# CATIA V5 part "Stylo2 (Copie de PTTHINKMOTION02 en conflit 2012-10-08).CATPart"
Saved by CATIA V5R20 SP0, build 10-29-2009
Part number: Stylo1.1
Bounding box of the stored display mesh (mm): x -5 to 5, y -3.274 to 25, z -5 to 5
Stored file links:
  D:\Dropbox\IAO\IAO_2010\iao\IAO OK\IAO_2010_1447_melguidj\Catia_1447_melguidj\Stylo2.CATPart
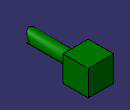
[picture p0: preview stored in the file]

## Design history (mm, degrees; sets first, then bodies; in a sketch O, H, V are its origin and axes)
Body1 (main body)
  Sketch1 on xy-plane, origin (0, 0, 0), H (1, 0, 0), V (0, 1, 0)
    point P1 (0, 15)
    line L1 (0, 15) -> (-2.5, 15)
    line L2 (-2.5, 15) -> (-2.5, -30)
    line L3 (0, -30) -> (0, 15)
    line L4 (0, -30) -> (-2.5, -30)
    distance L2 L3 = 2.5
    distance L1 H = 15
    distance L4 H = 30
    coincidence: P1 V
    horizontal: L1 H, L4 H
    vertical: L2 V, L3 V
  Shaft1: profile Sketch1, axis Sketch1.L3, angle 360
  Sketch2 on xy-plane, origin (0, 0, 0), H (1, 0, 0), V (0, 1, 0)
    point P1 (0, 0)
    point P2 (0, 10)
    distance P2 H = 10
    coincidence: P1 O, P2 V
  Sketch3 on face of Shaft1 from Sketch1.L1, origin (0, 15, 0), H (-1, 0, 0), V (0, 0, 1)
    line L1 (-5, 5) -> (5, 5)
    line L2 (5, 5) -> (5, -5)
    line L3 (5, -5) -> (-5, -5)
    line L4 (-5, -5) -> (-5, 5)
    length L2 = 10
    distance L1 H = 5
    length L1 = 10
    distance L2 V = 5
    horizontal: L1 H, L3 H
    vertical: L2 V, L4 V
  Pad1: profile Sketch3, direction (0, 1, 0), length 10
  Sketch4 on xy-plane, origin (0, 0, 0), H (1, 0, 0), V (0, 1, 0)
    arc A1 centre (0, -0.774) radius 2.5 from (-2.5, -0.774) to (0, -3.274) ccw
    point P1 (0, -0.774)
    point P2 (0, -3.274)
    point P3 (-2.5, -0.774)
    point P4 (-2.5, -0.774)
    line L1 (-2.5, -0.774) -> (-2.5, 3.2781)
    point P5 (-2.5, 3.2781)
    line L2 (-2.5, 3.2781) -> (-6.8161, 3.2781)
    point P6 (-6.8161, 3.2781)
    line L3 (-6.8161, 3.2781) -> (-6.8161, -43.1519)
    point P7 (-6.8161, -43.1519)
    line L4 (-6.8161, -43.1519) -> (0, -43.1519)
    axis line L5 (0, -5.8734) -> (0, -36.7849)
    point P8 (0, -5.8734)
    point P10 (0, -43.1519)
    point P12 (0, -3.274)
    point P13 (2.5, -0.774)
    point P14 (2.5, -0.774)
    point P15 (2.5, 3.2781)
    point P16 (6.8161, 3.2781)
    point P17 (6.8161, -43.1519)
    point P18 (0, -43.1519)
    arc A2 centre (0, -0.774) radius 2.5 from (2.5, -0.774) to (0, -3.274) cw
    line L6 (2.5, -0.774) -> (2.5, 3.2781)
    line L7 (2.5, 3.2781) -> (6.8161, 3.2781)
    line L8 (6.8161, 3.2781) -> (6.8161, -43.1519)
    line L9 (6.8161, -43.1519) -> (0, -43.1519)
    reference projected line E1 (-5, 15) -> (5, 15) from edge [start face of Pad1 | face of Pad1 from Sketch3.L1]
    distance L1 L5 = 2.5
    length L7 = 4.3161
    distance A1 L7 = 6.5521
    distance A1 E1 = 18.274
    coincidence: P1 V, P2 V, P4 A1, P8 V, L5 P10, P3 P4, P2 P12, P10 P18, P13 P14
    vertical: L1 V, L3 V, L5 V
    horizontal: L2 H, L4 H
    tangency: L1 A1
    symmetry: P2 P12 L5, P3 P13 L5, P4 P14 L5, P5 P15 L5, P6 P16 L5, P7 P17 L5, P10 P18 L5, A1 A2 L5, L1 L6 L5, L2 L7 L5, L3 L8 L5, L4 L9 L5
  Pocket1: profile Sketch4, direction (0, 0, -1), length 10, mirrored extent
